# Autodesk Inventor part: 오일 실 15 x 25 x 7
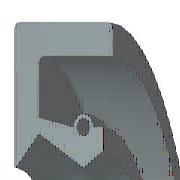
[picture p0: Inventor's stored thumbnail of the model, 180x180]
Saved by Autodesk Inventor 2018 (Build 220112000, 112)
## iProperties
Created: 2012-02
Part Number: 오일 실 15 x 25 x 7
Material: 고무
Description: 오일-실
Document SubType Name: Modeling
Standard: KS B 2804
Designer: mduedu
Standards Organization: KS
Language: ko-KR
Size Designation: D - 15 25 7
Categories: <MemberInstance><Categories><Category DisplayName="샤프트 부품" InternalName="7f7aeb1f-a693-4053-b835-cee3144e0d98" Mnemonic="SHFT"><Category DisplayName="실링" Intern
Density: 0.93 g/cm^3
Mass: 1.46464 g
Surface Area: 21.6685 cm^2
Volume: 1.57488 cm^3
Appearance: 고무 - 검은색 - 버전 1.1
IsCustomPart: 1
Author: mduedu
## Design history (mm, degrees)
revolve "본체" stored, may be unused: angle "d17" = 90 deg
revolve "스프링1" stored, may be unused: angle "d18" = 90 deg
body "Solid1"
sketch "스케치1"
  geometry: L1 (0, 12.5)-(7, 12.5); L2 (7, 10.75)-(1.75, 10.75); L3 (1.75, 9.25)-(4.9, 7.5); L4 (4.9, 7.5)-(0, 7.5); L5 (0, 0)-(9.586, 0) reference; L6 (4.9, 7.5)-(6.3, 8.375); L7 (0, 18)-(0, -3) reference; L8 (-1.941, 0)-(11.507, 0) reference; L9 (4.2, 9.6)-(1.75, 10.09); L10 (1.75, 10.09)-(1.75, 10.75); L11 (0, 12.5)-(0, 7.588); L12 (4.9, 7.5)-(0, 7.5); L13 (1.75, 9.25)-(0.152, 7.528); L14 (7, 12.5)-(7, 10.75); L15 (5.6, 9.6)-(6.3, 9.6); L16 (6.3, 9.6)-(6.3, 8.375); C1 r 0.455 at (4.9, 9.6); A1 r 0.7 centre (4.9, 9.6) between (5.6, 9.6) and (4.2, 9.6); A2 r 0.088 centre (0.088, 7.588) between (0, 7.588) and (0.152, 7.528); 1 further point
  constraints: 28 end point, 5 horizontal alignment, 5 point on line, 4 point on circle, 4 vertical alignment, 3 centre point, 3 tangent, 2 collinear, 2 horizontal, 2 perpendicular, 1 coincident, 1 parallel
  dimensions: "d0" = 25 diameter of L1 L5 (= SD2); "d1" = 1.75 distance of L1.end L2.start (= SD); "d2" = 0.91 diameter of C1 (= SPDI); "d3" = 1.4 diameter of A1 (= SPDA); "d4" = 15 diameter of L3.end L5 (= NND); "d5" = 18.5 diameter of L3.start L5 (= TKDM); "d7" = 20.18 diameter of L9.end L5 (= TKDM + 0.24 x SWDT); "d8" = 1.75 distance between parallel lines of L11 L10 (= SD); "d9" = 4.9 distance from line of L11 C1.centre (= SPDST); "d10" = 19.2 diameter of C1.centre L5 (= HLDM); "d11" = 0.0875 radius of A2 (= 0.25 x LAB); "d12" = 6.3 distance between parallel lines of L11 L16 (= SDI); "d13" = 16.75 diameter of L6.end L5 (= ABDM); "d14" = 7 distance from line of L11 L1.end (= SWDT)
fillet "모깎기1" dims "d6" = 0.3 (= RR)
other parameters: "SD2" = 25 [user parameter; used in 1 equation term], "SWDT" = 7 [user parameter; used in 2 equation terms], "RR" = 0.3 [user parameter; used in 1 equation term], "SD" = 1.75 [user parameter; used in 2 equation terms], "NND" = 15 [user parameter; used in 1 equation term], "SPDA" = 1.4 [user parameter; used in 1 equation term], "SPDI" = 0.91 [user parameter; used in 1 equation term], "TKDM" = 18.5 [user parameter; used in 2 equation terms], "HLDM" = 19.2 [user parameter; used in 1 equation term], "ABDM" = 16.75 [user parameter; used in 1 equation term], "SDI" = 6.3 [user parameter; used in 1 equation term], "SPDST" = 4.9 [user parameter; used in 1 equation term], "LAB" = 0.35 [user parameter; used in 1 equation term], "d15" = 0, "d16" = 0, "d19" = 0
